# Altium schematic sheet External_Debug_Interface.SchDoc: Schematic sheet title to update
size A4; Date: Not used; ApprovedBy: Not used; CheckedBy: Not used; Author: Not used; CompanyName: STMicroelectronics; DrawnBy: Not used; Engineer: Not used; Organization: Not used; Address1: Not used; Address2: Not used; Address3: Not used; Address4: Not used; DocumentNumber: Not used; Revision: Not used; SheetNumber: 7; SheetTotal: 7
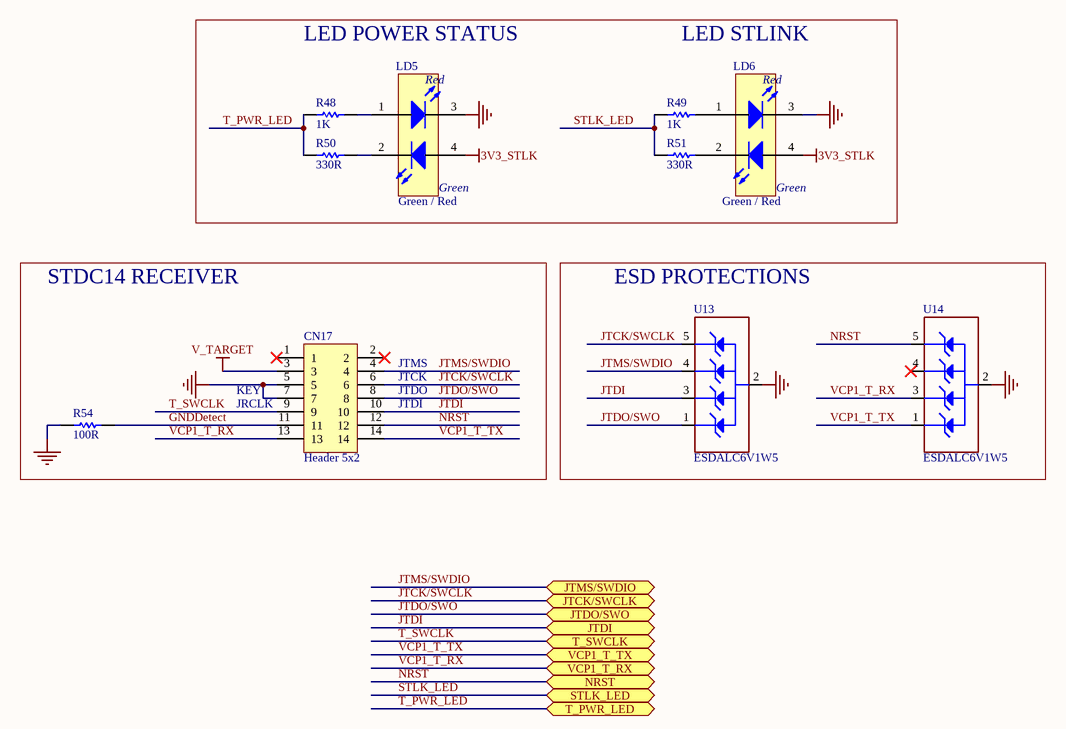
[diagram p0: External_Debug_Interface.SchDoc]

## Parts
CN17  value Header 5x2  [CON_STDC14_Receiver_MEDIUM_WITH_MIPI10_3D]  (hidden comment: Header 7x2)
LD5  value Green / Red  [LED_BI-GR_WE-150141SV73110]  (hidden comment: LED_BICOLOR)
LD6  value Green / Red  [LED_BI-GR_WE-150141SV73110]  (hidden comment: LED_BICOLOR)
R48  value 1K  [R0402]  (hidden comment: Resistor)
R49  value 1K  [R0402]  (hidden comment: Resistor)
R50  value 330R  [R0402]  (hidden comment: Resistor)
R51  value 330R  [R0402]  (hidden comment: Resistor)
R54  value 100R  [R0402]  (hidden comment: Resistor)
U13  ESDALC6V1W5  [ESD_SOT323-5L]
U14  ESDALC6V1W5  [ESD_SOT323-5L]

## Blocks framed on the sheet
STDC14 RECEIVER: CN17 R54
ESD PROTECTIONS: U13 U14

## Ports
JTCK/SWCLK (bidir), JTDI (bidir), JTDO/SWO (bidir), JTMS/SWDIO (bidir), NRST (bidir), STLK_LED (bidir), T_PWR_LED (bidir), T_SWCLK (bidir), VCP1_T_RX (bidir), VCP1_T_TX (bidir)

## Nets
3V3_STLK: LD5.4(Green_anode) LD6.4(Green_anode)
GND: CN17.5 CN17.7 LD5.3(RED_cathode) LD6.3(RED_cathode) R54.1 U13.2(GND) U14.2(GND)
V_TARGET: CN17.3
GNDDetect: CN17.11 R54.2
JTCK/SWCLK: CN17.6 U13.5(IO4) ; port JTCK/SWCLK
JTDI: CN17.10 U13.3(IO2) ; port JTDI
JTDO/SWO: CN17.8 U13.1(IO1) ; port JTDO/SWO
JTMS/SWDIO: CN17.4 U13.4(IO3) ; port JTMS/SWDIO
NRST: CN17.12 U14.5(IO4) ; port NRST
STLK_LED: R49.2 R51.1 ; port STLK_LED
T_PWR_LED: R48.2 R50.2 ; port T_PWR_LED
T_SWCLK: CN17.9 ; port T_SWCLK
VCP1_T_RX: CN17.13 U14.3(IO2) ; port VCP1_T_RX
VCP1_T_TX: CN17.14 U14.1(IO1) ; port VCP1_T_TX
NetLD5_1: LD5.1(Red_anode) R48.1
NetLD5_2: LD5.2(Green_cathode) R50.1
NetLD6_1: LD6.1(Red_anode) R49.1
NetLD6_2: LD6.2(Green_cathode) R51.2

Not connected (* = marked no-connect by the designer): CN17 1* 2*; U14 4(IO3)*

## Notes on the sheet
- LED POWER STATUS
- LED STLINK
- (near CN17) JRCLK
- (near CN17) KEY
- (near CN17) JTMS
- (near CN17) JTCK
- (near CN17) JTDO
- (near CN17) JTDI

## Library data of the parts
CN17 = MCD-01226: Header, 5x2, 1.27mm, VR, SMD, T=5.97mm/3.05mm; Part_Type: Connector; Part_Preference: Recommended; Manufacturer: SAMTEC; Manufacturer_Part_Number: FTSH-105-01-L-DV-K; Order_Code_RS: 159-2332; Component_Country_Of_Origin: China, Costa Rica, Malaysia, United States, Vietnam
LD5 LD6 = MCD-02631: LED Bicolor, Green/Red, 2V, 20mA,  4-PLCC; Part_Type: Display; Part_Preference: Recommended; Manufacturer: WURTH ELEKTRONIK; Manufacturer_Part_Number: 150141SV73110; Order_Code_RS: 184-6963
R48 = MCD-02665: Resistor, 1K, 0402, +/-0.1%, 1/16W, +/-25ppm/°C; Part_Preference: Recommended; Manufacturer: YAGEO; Manufacturer_Part_Number: RT0402BRD071KL; Order_Code_RS: 199-1298; Component_Country_Of_Origin: Taiwan; ShowFields: YES; ID: 4771
R49 = MCD-02665: Resistor, 1K, 0402, +/-0.1%, 1/16W, +/-25ppm/°C; Part_Preference: Recommended; Manufacturer: YAGEO; Manufacturer_Part_Number: RT0402BRD071KL; Order_Code_RS: 199-1298
R50 R51 = MCD-00062: Resistor, 330R, 0402, +/-1%, 1/16W; Part_Preference: Recommended; Manufacturer: YAGEO; Manufacturer_Part_Number: RC0402FR-07330RL; Component_Country_Of_Origin: China
R54 = MCD-00067: Resistor, 100R, 0402, +/- 1%, 1/16W; Part_Preference: Recommended; Manufacturer: YAGEO; Manufacturer_Part_Number: RC0402FR-07100RL; Order_Code_RS: 9239111; Component_Country_Of_Origin: China; ShowFields: YES; ID: 2527
U13 U14 = MCD-00136: Dual Transil array for ESD protection; BMS_Part_Number: 9151112; Part_Type: Diode; Part_Preference: Recommended; Manufacturer: STMICROELECTRONICS; Manufacturer_HQ_COO: EU; Component_Country_Of_Origin: China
